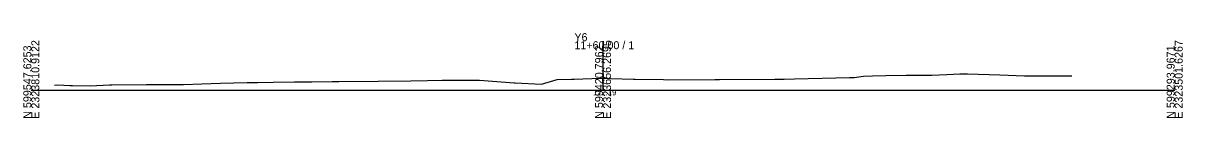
# Model space of a CAD drawing. Extents: x -26 to 3203, y -10 to 2019.
# Drawn here: x 1397.2 to 1802.8, y -9.7 to 19.9 of the extents above; entities that cross this region are included whole.
import ezdxf

# ---------------------------------------------------------------- set-up
doc = ezdxf.new("R2010")
doc.units = 0
for name, color, linetype in [('Default', 7, 'Continuous'), ('Exist CMT Pavement', 7, 'Continuous'), ('Exist Cross Section Cell', 7, 'Continuous'), ('Exist XS Center Line Elevation Label', 7, 'Continuous'), ('Exist XS Ground Line', 7, 'Continuous'), ('Prop XS Earthwork Shape', 7, 'Continuous')]:
    doc.layers.add(name, color=color, linetype=linetype)

msp = doc.modelspace()

# ---------------------------------------------------------------- linework, layer by layer
at = {"layer": 'Exist CMT Pavement'}
for points in [[(1599.9, 4.18), (1599.9, 4.29), (1600, 4.29), (1600, 4.19)], [(1600, 4.19), (1600, 4.29), (1600.1, 4.29), (1600.1, 4.19)]]:
    msp.add_lwpolyline(points, dxfattribs=at)
at = {"layer": 'Exist Cross Section Cell'}
for p, q in [((1600, 0), (1600, 17.09)), ((1400, 0), (1600, 0)), ((1600, 0), (1800, 0))]:
    msp.add_line(p, q, dxfattribs=at)
at = {"layer": 'Exist XS Ground Line'}
msp.add_lwpolyline([(1408.14, 1.74), (1409.26, 1.8), (1413.52, 1.67), (1414.44, 1.64), (1420.63, 1.5), (1427.38, 1.88), (1427.73, 1.89), (1428.17, 1.9), (1440.31, 1.96), (1443.94, 1.99), (1453.25, 2.01), (1459.71, 2.18), (1466.18, 2.4), (1475.48, 2.69), (1479.11, 2.73), (1484.59, 2.75), (1492.05, 2.85), (1498.16, 2.93), (1505.3, 2.98), (1507.54, 2.99), (1521.32, 3.18), (1532.72, 3.23), (1538.57, 3.36), (1543.79, 3.46), (1554.34, 3.51), (1555.65, 3.49), (1556.8, 3.44), (1568.9, 2.6), (1569.22, 2.58), (1578.47, 2.04), (1583.94, 3.7), (1588.97, 3.79), (1589.96, 3.81), (1599.17, 4.15), (1600, 4.19), (1600.34, 4.2), (1602.64, 4.11), (1610.63, 3.8), (1611.31, 3.79), (1621.22, 3.67), (1622.61, 3.66), (1639.15, 3.69), (1640.29, 3.71), (1640.73, 3.7), (1660.06, 3.88), (1663.41, 3.88), (1667, 3.95), (1686.22, 4.41), (1687.84, 4.45), (1691.16, 4.83), (1694.25, 4.96), (1698.9, 5.08), (1706.07, 5.23), (1710.69, 5.23), (1715.09, 5.21), (1720.26, 5.49), (1722.47, 5.58), (1724.81, 5.7), (1727.52, 5.69), (1738.84, 5.39), (1747.48, 5.01), (1761.83, 5), (1764.05, 4.98)], dxfattribs=at)
at = {"layer": 'Prop XS Earthwork Shape'}
for points in [[(1600, 4.29), (1600, 4.19), (1599.9, 4.18), (1599.9, 4.29)], [(1600.1, 4.29), (1600.1, 4.19), (1600, 4.19), (1600, 4.29)]]:
    msp.add_lwpolyline(points, close=True, dxfattribs=at)

# ---------------------------------------------------------------- texts
at = {"layer": 'Default'}
msp.add_text('-', height=0.0001, dxfattribs=at).set_placement((1400, 0))
at = {"layer": 'Exist Cross Section Cell'}
for s, p in [('E 2323810.9122', (1402.8, -10)), ('E 2323656.2695', (1602.8, -10)), ('E 2323501.6267', (1802.8, -10)), ('N 599547.6253', (1400, -10)), ('N 599420.7962', (1600, -10)), ('N 599293.9671', (1800, -10))]:
    msp.add_text(s, height=2.8, rotation=90, dxfattribs=at).set_placement(p)
for s, p in [('Y6', (1590, 17.09)), ('11+60.00 / 1', (1590, 14.29))]:
    msp.add_text(s, height=2.8, dxfattribs=at).set_placement(p)
at = {"layer": 'Exist XS Center Line Elevation Label'}
msp.add_text('122.19', height=2, dxfattribs=at).set_placement((1596.49, -1.81))

doc.saveas('drawing.dxf')
